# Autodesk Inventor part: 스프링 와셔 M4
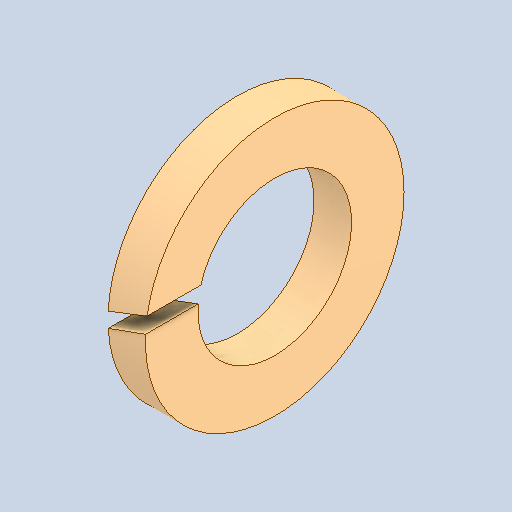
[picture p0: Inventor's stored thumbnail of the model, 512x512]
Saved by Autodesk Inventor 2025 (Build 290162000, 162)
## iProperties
Created: 2026-03
Part Number: 스프링 와셔 M4
Material: 강철, 연강
Description: 스프링 잠금 와셔
Document SubType Name: Modeling
Designer: KDI
Density: 7.85 g/cm^3
Appearance: 기본값
Author: jhkim
Sending System: Autodesk Inventor 2026
Preprocessor: ST-DEVELOPER v20.1
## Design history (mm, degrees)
feature "Solid1"
node "솔리드1"
